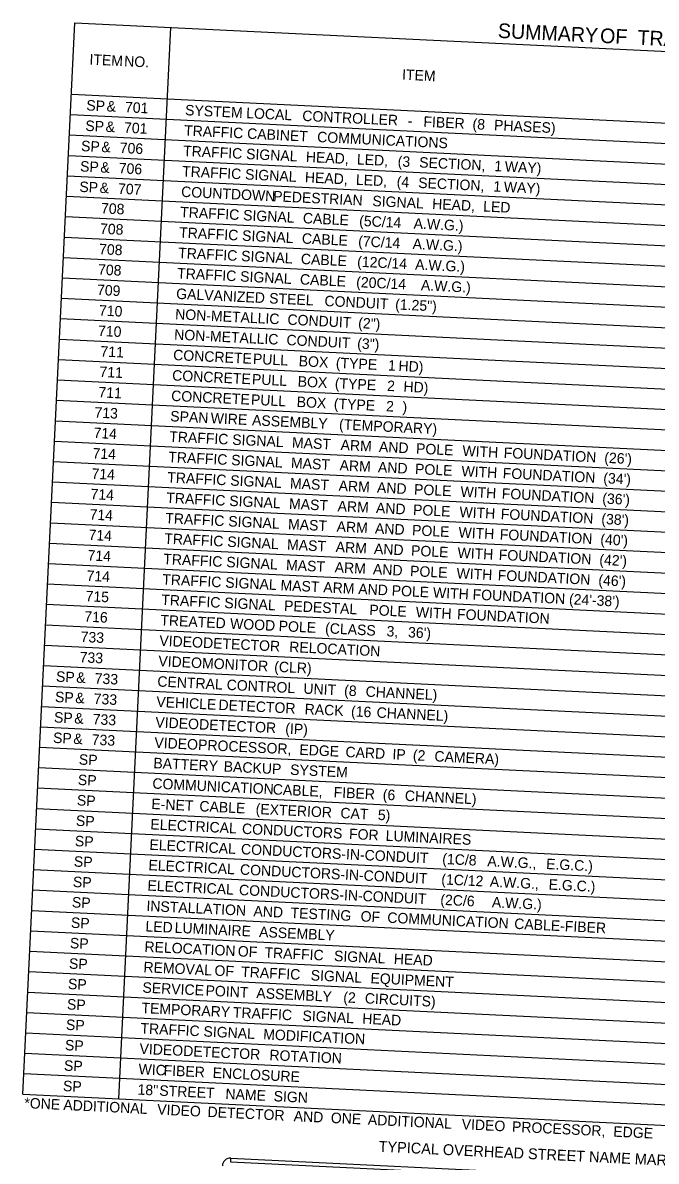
# Model space of a CAD drawing. Extents: x 669100 to 670534, y 743337 to 744379.
# Drawn here: x 669399.1 to 669545.5, y 743470.3 to 743733.5 of the extents above; entities that cross this region are included whole.
import ezdxf

# ---------------------------------------------------------------- set-up
doc = ezdxf.new("R2010")
doc.units = 0
for name, color, linetype in [('R_Dimension', 7, 'Continuous'), ('R_Proposed Road Annot', 7, 'Continuous'), ('rd_ML Pavement Edge_p_n', 7, 'Continuous')]:
    doc.layers.add(name, color=color, linetype=linetype)

msp = doc.modelspace()

# ---------------------------------------------------------------- linework, layer by layer
at = {"layer": 'R_Dimension'}
for p, q in [((669399.11, 743485.86), (669411.13, 743733.5)), ((669411.13, 743733.5), (669722.26, 743718.39)), ((669421.28, 743484.78), (669433.3, 743732.43)), ((669410.33, 743716.99), (669721.46, 743701.89)), ((669410.1, 743712.28), (669721.23, 743697.17)), ((669409.87, 743707.56), (669721, 743692.45)), ((669409.64, 743702.84), (669720.77, 743687.73)), ((669409.41, 743698.13), (669720.54, 743683.02)), ((669409.18, 743693.41), (669720.31, 743678.3)), ((669408.96, 743688.69), (669720.08, 743673.58)), ((669408.73, 743683.97), (669719.86, 743668.87)), ((669408.5, 743679.26), (669719.63, 743664.15)), ((669408.27, 743674.54), (669719.4, 743659.43)), ((669408.04, 743669.82), (669719.17, 743654.72)), ((669407.81, 743665.11), (669718.94, 743650)), ((669407.58, 743660.39), (669718.71, 743645.28)), ((669407.35, 743655.67), (669718.48, 743640.56)), ((669407.12, 743650.96), (669718.25, 743635.85)), ((669406.89, 743646.24), (669718.02, 743631.13)), ((669406.66, 743641.52), (669717.79, 743626.41)), ((669406.44, 743636.8), (669717.57, 743621.7)), ((669406.21, 743632.09), (669717.34, 743616.98)), ((669405.98, 743627.37), (669717.11, 743612.26)), ((669405.75, 743622.65), (669716.88, 743607.54)), ((669405.52, 743617.94), (669716.65, 743602.83)), ((669405.29, 743613.22), (669716.42, 743598.11)), ((669405.06, 743608.5), (669716.19, 743593.39)), ((669404.83, 743603.79), (669715.96, 743588.68)), ((669404.6, 743599.07), (669715.73, 743583.96)), ((669404.37, 743594.35), (669715.5, 743579.24)), ((669404.15, 743589.63), (669715.27, 743574.53)), ((669403.92, 743584.92), (669715.05, 743569.81)), ((669403.69, 743580.2), (669714.82, 743565.09)), ((669403.46, 743575.48), (669714.59, 743560.37)), ((669403.23, 743570.77), (669714.36, 743555.66)), ((669403, 743566.05), (669714.13, 743550.94)), ((669402.77, 743561.33), (669713.9, 743546.22)), ((669402.54, 743556.61), (669713.67, 743541.51)), ((669402.31, 743551.9), (669713.44, 743536.79)), ((669402.08, 743547.18), (669713.21, 743532.07)), ((669401.85, 743542.46), (669712.98, 743527.36)), ((669401.63, 743537.75), (669712.75, 743522.64)), ((669401.4, 743533.03), (669712.53, 743517.92)), ((669401.17, 743528.31), (669712.3, 743513.2)), ((669400.94, 743523.6), (669712.07, 743508.49)), ((669400.71, 743518.88), (669711.84, 743503.77)), ((669400.48, 743514.16), (669711.61, 743499.05)), ((669400.25, 743509.44), (669711.38, 743494.34)), ((669400.02, 743504.73), (669711.15, 743489.62)), ((669399.79, 743500.01), (669710.92, 743484.9)), ((669399.56, 743495.29), (669710.69, 743480.19)), ((669399.33, 743490.58), (669710.46, 743475.47)), ((669399.11, 743485.86), (669710.24, 743470.75))]:
    msp.add_line(p, q, dxfattribs=at)
at = {"layer": 'rd_ML Pavement Edge_p_n'}
msp.add_line((669447.16, 743470.1), (669447.2, 743471.03), dxfattribs=at)
msp.add_lwpolyline([(669525.81, 743466.28), (669447.16, 743470.1), (669447.2, 743471.03), (669525.86, 743467.21), (669525.81, 743466.28)], close=True, dxfattribs=at)
msp.add_arc((669447.11, 743469.16), 1.88, 87.2201, 177.2198, dxfattribs=at)

# ---------------------------------------------------------------- texts
at = {"layer": 'R_Dimension'}
for s, height, p in [('SUMMARY', 3.391, (669508.83, 743730.02)), (' OF', 3.391, (669531.18, 743728.93)), (' TRAFFIC', 3.391, (669539.82, 743728.51)), ('ITEM', 2.422, (669414.47, 743723.85)), (' NO.', 2.422, (669421.59, 743723.51)), ('ITEM', 2.422, (669486.71, 743720.35)), ('SP', 2.422, (669413.75, 743713.25)), (' &', 2.422, (669417.54, 743713.07)), (' 701', 2.422, (669421.78, 743712.86)), ('SYSTEM', 2.422, (669436.57, 743712.14)), (' LOCAL', 2.422, (669449.79, 743711.5)), (' CONTROLLER', 2.4218, (669462.76, 743710.87)), ('SP', 2.422, (669413.52, 743708.53)), (' &', 2.422, (669417.31, 743708.35)), (' 701', 2.422, (669421.56, 743708.14)), (' -', 2.422, (669487.14, 743709.69)), (' FIBER', 2.422, (669490.74, 743709.51)), (' (8', 2.422, (669502.09, 743708.96)), (' PHASES)', 2.422, (669507.07, 743708.72)), ('TRAFFIC', 2.422, (669436.34, 743707.43)), (' CABINET', 2.422, (669450, 743706.76)), (' COMMUNICATIONS', 2.4218, (669466.19, 743705.98)), ('SP', 2.422, (669412.54, 743703.85)), (' &', 2.422, (669416.33, 743703.67)), (' 706', 2.422, (669420.57, 743703.46)), ('TRAFFIC', 2.422, (669436.11, 743702.71)), (' SIGNAL', 2.422, (669449.77, 743702.05)), (' HEAD,', 2.422, (669463.58, 743701.38)), (' LED,', 2.422, (669475.37, 743700.8)), (' (3', 2.422, (669484.8, 743700.34)), (' SECTION,', 2.422, (669489.77, 743700.1)), ('SP', 2.422, (669412.31, 743699.14)), (' &', 2.422, (669416.1, 743698.95)), (' 706', 2.422, (669420.34, 743698.75)), ('TRAFFIC', 2.422, (669435.88, 743697.99)), (' SIGNAL', 2.422, (669449.54, 743697.33)), (' 1', 2.422, (669507.12, 743699.26)), (' WAY)', 2.422, (669509.54, 743699.14)), (' HEAD,', 2.422, (669463.35, 743696.66)), (' LED,', 2.422, (669475.14, 743696.09)), (' (4', 2.422, (669484.57, 743695.63)), (' SECTION,', 2.422, (669489.54, 743695.39)), ('SP', 2.422, (669412.14, 743694.42)), (' &', 2.422, (669415.93, 743694.23)), (' 707', 2.422, (669420.18, 743694.03)), ('COUNTDOWN', 2.422, (669435.66, 743693.27)), (' PEDESTRIAN', 2.4218, (669456.02, 743692.29)), (' 1', 2.422, (669506.89, 743694.54)), (' WAY)', 2.422, (669509.31, 743694.43)), ('708', 2.422, (669417.14, 743689.45)), (' SIGNAL', 2.422, (669478.95, 743691.17)), (' HEAD,', 2.422, (669492.76, 743690.5)), (' LED', 2.422, (669504.55, 743689.93)), ('TRAFFIC', 2.422, (669435.43, 743688.56)), (' SIGNAL', 2.422, (669449.08, 743687.89)), (' CABLE', 2.422, (669462.89, 743687.22)), ('708', 2.422, (669416.91, 743684.73)), (' (5C/14', 2.422, (669475.9, 743686.59)), (' A.W.G.)', 2.422, (669488.49, 743685.98)), ('TRAFFIC', 2.422, (669435.2, 743683.84)), (' SIGNAL', 2.422, (669448.85, 743683.18)), (' CABLE', 2.422, (669462.66, 743682.51)), (' (7C/14', 2.422, (669475.67, 743681.88)), ('708', 2.422, (669416.69, 743680.01)), ('TRAFFIC', 2.422, (669434.97, 743679.12)), (' A.W.G.)', 2.422, (669488.26, 743681.26)), (' SIGNAL', 2.422, (669448.63, 743678.46)), (' CABLE', 2.422, (669462.43, 743677.79)), (' (12C/14', 2.422, (669475.44, 743677.16)), (' A.W.G.)', 2.422, (669488.83, 743676.51)), ('708', 2.422, (669416.46, 743675.29)), ('TRAFFIC', 2.422, (669434.74, 743674.41)), (' SIGNAL', 2.422, (669448.4, 743673.74)), (' CABLE', 2.422, (669462.21, 743673.07)), (' (20C/14', 2.422, (669475.21, 743672.44)), (' A.W.G.)', 2.422, (669490.17, 743671.72)), ('709', 2.422, (669416.22, 743670.58)), ('GALVANIZED', 2.422, (669434.51, 743669.69)), (' STEEL', 2.422, (669455.1, 743668.69)), ('710', 2.422, (669416.67, 743665.83)), (' CONDUIT', 2.422, (669467.88, 743668.07)), (' (1.25")', 2.422, (669484.22, 743667.28)), ('NON-METALLIC', 2.4218, (669434.28, 743664.97)), (' CONDUIT', 2.422, (669459.33, 743663.76)), ('710', 2.422, (669416.45, 743661.11)), (' (2")', 2.422, (669475.67, 743662.96)), ('NON-METALLIC', 2.4218, (669434.05, 743660.26)), (' CONDUIT', 2.422, (669459.1, 743659.04)), (' (3")', 2.422, (669475.44, 743658.25)), ('711', 2.422, (669417.01, 743656.36)), ('CONCRETE', 2.422, (669433.82, 743655.54)), (' PULL', 2.422, (669451.35, 743654.69)), (' BOX', 2.422, (669461.92, 743654.17)), (' (TYPE', 2.422, (669470.51, 743653.76)), (' 1', 2.422, (669482.56, 743653.17)), (' HD)', 2.422, (669484.98, 743653.05)), ('711', 2.422, (669416.78, 743651.64)), ('CONCRETE', 2.422, (669433.59, 743650.82)), (' PULL', 2.422, (669451.12, 743649.97)), (' BOX', 2.422, (669461.69, 743649.46)), (' (TYPE', 2.422, (669470.28, 743649.04)), (' 2', 2.422, (669482.34, 743648.45)), (' HD)', 2.422, (669486.13, 743648.27)), ('711', 2.422, (669416.55, 743646.92)), ('CONCRETE', 2.422, (669433.36, 743646.1)), (' PULL', 2.422, (669450.89, 743645.25)), (' BOX', 2.422, (669461.46, 743644.74)), ('713', 2.422, (669415.63, 743642.24)), (' (TYPE', 2.422, (669470.05, 743644.32)), (' 2', 2.422, (669482.11, 743643.74)), (' )', 2.422, (669485.9, 743643.55)), ('SPAN', 2.422, (669433.14, 743641.39)), (' WIRE', 2.422, (669441.57, 743640.98)), (' ASSEMBLY', 2.422, (669451.15, 743640.51)), (' (TEMPORARY)', 2.4218, (669471.25, 743639.54)), ('714', 2.422, (669415.41, 743637.52)), ('TRAFFIC', 2.422, (669432.91, 743636.67)), (' SIGNAL', 2.422, (669446.56, 743636.01)), (' MAST', 2.422, (669460.37, 743635.34)), (' ARM', 2.422, (669471.61, 743634.79)), (' AND', 2.422, (669480.47, 743634.36)), ('714', 2.422, (669415.18, 743632.8)), ('TRAFFIC', 2.422, (669432.68, 743631.95)), (' POLE', 2.422, (669489.04, 743633.94)), (' WITH', 2.422, (669499.76, 743633.42)), (' FOUNDATION', 2.4218, (669509.3, 743632.96)), (" (26')", 2.422, (669532.54, 743631.83)), (' SIGNAL', 2.422, (669446.33, 743631.29)), (' MAST', 2.422, (669460.14, 743630.62)), (' ARM', 2.422, (669471.38, 743630.07)), (' AND', 2.422, (669480.24, 743629.64)), (' POLE', 2.422, (669488.81, 743629.23)), ('714', 2.422, (669414.95, 743628.09)), ('TRAFFIC', 2.422, (669432.45, 743627.24)), (' SIGNAL', 2.422, (669446.11, 743626.57)), (' WITH', 2.422, (669499.53, 743628.71)), (' FOUNDATION', 2.4218, (669509.08, 743628.24)), (" (34')", 2.422, (669532.31, 743627.12)), (' MAST', 2.422, (669459.91, 743625.9)), (' ARM', 2.422, (669471.15, 743625.36)), (' AND', 2.422, (669480.01, 743624.93)), (' POLE', 2.422, (669488.58, 743624.51)), (' WITH', 2.422, (669499.3, 743623.99)), ('714', 2.422, (669414.72, 743623.37)), ('TRAFFIC', 2.422, (669432.22, 743622.52)), (' SIGNAL', 2.422, (669445.88, 743621.86)), (' MAST', 2.422, (669459.69, 743621.19)), (' FOUNDATION', 2.4218, (669508.85, 743623.53)), (" (36')", 2.422, (669532.08, 743622.4)), ('714', 2.422, (669414.49, 743618.65)), (' ARM', 2.422, (669470.92, 743620.64)), (' AND', 2.422, (669479.78, 743620.21)), (' POLE', 2.422, (669488.35, 743619.79)), (' WITH', 2.422, (669499.07, 743619.27)), (' FOUNDATION', 2.4218, (669508.62, 743618.81)), ('TRAFFIC', 2.422, (669431.99, 743617.8)), (' SIGNAL', 2.422, (669445.65, 743617.14)), (' MAST', 2.422, (669459.46, 743616.47)), (' ARM', 2.422, (669470.69, 743615.92)), (" (38')", 2.422, (669531.86, 743617.68)), ('714', 2.422, (669414.26, 743613.94)), ('TRAFFIC', 2.422, (669431.76, 743613.09)), (' AND', 2.422, (669479.55, 743615.49)), (' POLE', 2.422, (669488.12, 743615.08)), (' WITH', 2.422, (669498.85, 743614.56)), (' FOUNDATION', 2.4218, (669508.39, 743614.09)), (' SIGNAL', 2.422, (669445.42, 743612.42)), (' MAST', 2.422, (669459.23, 743611.75)), (' ARM', 2.422, (669470.47, 743611.21)), (' AND', 2.422, (669479.32, 743610.78)), (" (40')", 2.422, (669531.63, 743612.96)), ('714', 2.422, (669414.03, 743609.22)), ('TRAFFIC', 2.422, (669431.53, 743608.37)), (' POLE', 2.422, (669487.89, 743610.36)), (' WITH', 2.422, (669498.62, 743609.84)), (' FOUNDATION', 2.4218, (669508.16, 743609.38)), (" (42')", 2.422, (669531.4, 743608.25)), (' SIGNAL', 2.422, (669445.19, 743607.71)), (' MAST', 2.422, (669459, 743607.03)), (' ARM', 2.422, (669470.24, 743606.49)), (' AND', 2.422, (669479.09, 743606.06)), (' POLE', 2.422, (669487.66, 743605.64)), ('714', 2.422, (669413.8, 743604.5)), ("TRAFFIC SIGNAL MAST ARM AND POLE WITH FOUNDATION (24'-38')", 2.4218, (669431.3, 743603.65)), (' WITH', 2.422, (669498.39, 743605.12)), (' FOUNDATION', 2.4218, (669507.93, 743604.66)), (" (46')", 2.422, (669531.17, 743603.53)), ('715', 2.422, (669413.57, 743599.78)), ('TRAFFIC', 2.422, (669431.07, 743598.93)), (' SIGNAL', 2.422, (669444.73, 743598.27)), (' PEDESTAL', 2.422, (669458.54, 743597.6)), ('716', 2.422, (669413.28, 743595.07)), (' POLE', 2.422, (669478.25, 743596.64)), (' WITH', 2.422, (669488.98, 743596.12)), (' FOUNDATION', 2.4218, (669498.52, 743595.66)), ('TREATED', 2.422, (669430.85, 743594.22)), (' WOOD', 2.422, (669446.06, 743593.48)), (' POLE', 2.422, (669457.3, 743592.93)), (' (CLASS', 2.422, (669468.03, 743592.41)), ('733', 2.422, (669412.43, 743590.38)), ('VIDEO', 2.422, (669430.62, 743589.5)), (' 3,', 2.422, (669482.22, 743591.72)), (" 36')", 2.422, (669487.19, 743591.48)), (' DETECTOR', 2.422, (669439.82, 743589.05)), (' RELOCATION', 2.4218, (669459.74, 743588.09)), ('733', 2.422, (669412.2, 743585.67)), ('VIDEO', 2.422, (669430.39, 743584.78)), (' MONITOR', 2.422, (669439.59, 743584.34)), (' (CLR)', 2.422, (669456.27, 743583.53)), ('SP', 2.422, (669406.74, 743581.2)), (' &', 2.422, (669410.53, 743581.02)), (' 733', 2.422, (669414.78, 743580.81)), ('CENTRAL', 2.422, (669430.16, 743580.07)), (' CONTROL', 2.422, (669445.28, 743579.33)), ('SP', 2.422, (669406.51, 743576.49)), (' &', 2.422, (669410.3, 743576.3)), (' UNIT', 2.422, (669463.01, 743578.47)), (' (8', 2.422, (669472.42, 743578.01)), (' CHANNEL)', 2.422, (669477.39, 743577.77)), (' 733', 2.422, (669414.55, 743576.1)), ('VEHICLE', 2.422, (669429.93, 743575.35)), (' DETECTOR', 2.422, (669443.38, 743574.7)), (' RACK', 2.422, (669463.3, 743573.73)), ('SP', 2.422, (669406.28, 743571.77)), (' &', 2.422, (669410.07, 743571.59)), (' 733', 2.422, (669414.32, 743571.38)), (' (16', 2.422, (669474.02, 743573.21)), (' CHANNEL)', 2.422, (669479.93, 743572.92)), ('VIDEO', 2.422, (669429.7, 743570.63)), (' DETECTOR', 2.422, (669438.9, 743570.19)), (' (IP)', 2.422, (669458.82, 743569.22)), ('SP', 2.422, (669406.06, 743567.05)), (' &', 2.422, (669409.85, 743566.87)), (' 733', 2.422, (669414.09, 743566.66)), ('VIDEO', 2.422, (669429.47, 743565.92)), (' PROCESSOR,', 2.4218, (669438.67, 743565.47)), (' EDGE', 2.422, (669462.08, 743564.33)), (' CARD', 2.422, (669472.73, 743563.81)), (' IP', 2.422, (669483.58, 743563.29)), (' (2', 2.422, (669488.31, 743563.06)), ('SP', 2.422, (669412.02, 743562.03)), ('BATTERY', 2.422, (669429.24, 743561.2)), (' BACKUP', 2.422, (669444.59, 743560.45)), (' CAMERA)', 2.422, (669493.28, 743562.82)), (' SYSTEM', 2.422, (669459.95, 743559.71)), ('SP', 2.422, (669411.79, 743557.32)), ('COMMUNICATION', 2.4218, (669429.01, 743556.48)), (' CABLE,', 2.422, (669455.93, 743555.17)), ('SP', 2.422, (669411.56, 743552.6)), (' FIBER', 2.422, (669470, 743554.49)), (' (6', 2.422, (669481.35, 743553.94)), (' CHANNEL)', 2.422, (669486.46, 743553.69)), ('E-NET', 2.422, (669428.78, 743551.76)), (' CABLE', 2.422, (669438.97, 743551.27)), (' (EXTERIOR', 2.422, (669451.98, 743550.64)), ('SP', 2.422, (669411.33, 743547.88)), (' CAT', 2.422, (669471.56, 743549.69)), (' 5)', 2.422, (669480.21, 743549.27)), ('ELECTRICAL', 2.422, (669428.55, 743547.05)), (' CONDUCTORS', 2.4218, (669448.82, 743546.06)), (' FOR', 2.422, (669473.56, 743544.86)), ('SP', 2.422, (669411.1, 743543.17)), ('ELECTRICAL', 2.422, (669428.33, 743542.33)), (' LUMINAIRES', 2.4218, (669482.02, 743544.45)), (' CONDUCTORS-IN-CONDUIT', 2.4218, (669448.59, 743541.35)), ('SP', 2.422, (669410.87, 743538.45)), ('ELECTRICAL', 2.422, (669428.1, 743537.61)), (' (1C/8', 2.422, (669495.1, 743539.09)), (' A.W.G.,', 2.422, (669505.52, 743538.58)), (' E.G.C.)', 2.422, (669519.1, 743537.92)), (' CONDUCTORS-IN-CONDUIT', 2.4218, (669448.36, 743536.63)), (' (1C/12', 2.422, (669494.88, 743534.37)), ('SP', 2.422, (669410.64, 743533.73)), ('ELECTRICAL', 2.422, (669427.87, 743532.9)), (' CONDUCTORS-IN-CONDUIT', 2.4218, (669448.13, 743531.91)), (' A.W.G.,', 2.422, (669506.09, 743533.83)), (' E.G.C.)', 2.422, (669519.68, 743533.17)), ('SP', 2.422, (669410.41, 743529.02)), (' (2C/6', 2.422, (669494.65, 743529.65)), (' A.W.G.)', 2.422, (669506.57, 743529.07)), ('INSTALLATION', 2.4218, (669427.64, 743528.18)), (' AND', 2.422, (669451.47, 743527.02)), (' TESTING', 2.422, (669460.04, 743526.61)), ('SP', 2.422, (669410.18, 743524.3)), (' OF', 2.422, (669476.23, 743525.82)), (' COMMUNICATION', 2.4218, (669482.4, 743525.52)), (' CABLE-FIBER', 2.4218, (669511.73, 743524.1)), ('LED', 2.422, (669427.41, 743523.46)), (' LUMINAIRE', 2.422, (669433.26, 743523.18)), (' ASSEMBLY', 2.422, (669452.78, 743522.23)), ('SP', 2.422, (669409.95, 743519.58)), ('RELOCATION', 2.422, (669427.18, 743518.75)), (' OF', 2.422, (669447.85, 743517.74)), (' TRAFFIC', 2.422, (669454.02, 743517.44)), (' SIGNAL', 2.422, (669470.09, 743516.66)), (' HEAD', 2.422, (669483.9, 743515.99)), ('SP', 2.422, (669409.73, 743514.86)), ('REMOVAL', 2.422, (669426.95, 743514.03)), (' OF', 2.422, (669442.46, 743513.28)), (' TRAFFIC', 2.422, (669448.63, 743512.98)), (' SIGNAL', 2.422, (669464.7, 743512.19)), (' EQUIPMENT', 2.422, (669478.51, 743511.52)), ('SP', 2.422, (669409.5, 743510.15)), ('SERVICE', 2.422, (669426.72, 743509.31)), (' POINT', 2.422, (669440.4, 743508.65)), (' ASSEMBLY', 2.422, (669452.13, 743508.08)), ('SP', 2.422, (669409.27, 743505.43)), (' (2', 2.422, (669472.23, 743507.1)), (' CIRCUITS)', 2.422, (669477.2, 743506.86)), ('TEMPORARY', 2.422, (669426.49, 743504.59)), (' TRAFFIC', 2.422, (669446.72, 743503.61)), (' SIGNAL', 2.422, (669462.8, 743502.83)), ('SP', 2.422, (669409.04, 743500.71)), ('TRAFFIC', 2.422, (669426.26, 743499.88)), (' HEAD', 2.422, (669476.61, 743502.16)), (' SIGNAL', 2.422, (669439.92, 743499.21)), (' MODIFICATION', 2.4218, (669453.73, 743498.54)), ('SP', 2.422, (669408.81, 743496)), ('VIDEO', 2.422, (669426.04, 743495.16)), (' DETECTOR', 2.422, (669435.23, 743494.71)), (' ROTATION', 2.422, (669455.16, 743493.75)), ('SP', 2.422, (669408.58, 743491.28)), ('WIC', 2.422, (669425.81, 743490.44)), (' FIBER', 2.422, (669430.7, 743490.21)), (' ENCLOSURE', 2.422, (669442.05, 743489.65)), ('SP', 2.422, (669408.35, 743486.56)), ('18"', 2.422, (669425.58, 743485.73)), (' STREET', 2.422, (669429.71, 743485.53)), (' NAME', 2.422, (669444.99, 743484.78)), (' SIGN', 2.422, (669456.13, 743484.24)), ('*ONE', 2.422, (669399.42, 743482.62)), (' ADDITIONAL', 2.4218, (669407.54, 743482.23)), (' VIDEO', 2.422, (669429.23, 743481.17)), (' DETECTOR', 2.422, (669440.85, 743480.61)), (' AND', 2.422, (669460.77, 743479.64)), (' ONE', 2.422, (669469.34, 743479.23)), (' ADDITIONAL', 2.4218, (669477.9, 743478.81)), (' VIDEO', 2.422, (669499.59, 743477.76)), (' PROCESSOR,', 2.4218, (669511.21, 743477.19)), (' EDGE', 2.422, (669534.62, 743476.06))]:
    msp.add_text(s, height=height, rotation=357.2199, dxfattribs=at).set_placement(p)
at = {"layer": 'R_Proposed Road Annot'}
msp.add_text('TYPICAL OVERHEAD STREET NAME MARKER MAST ARM MOUNTED', height=2.5, rotation=357.2199, dxfattribs=at).set_placement((669481.29, 743472.53))

doc.saveas('drawing.dxf')
